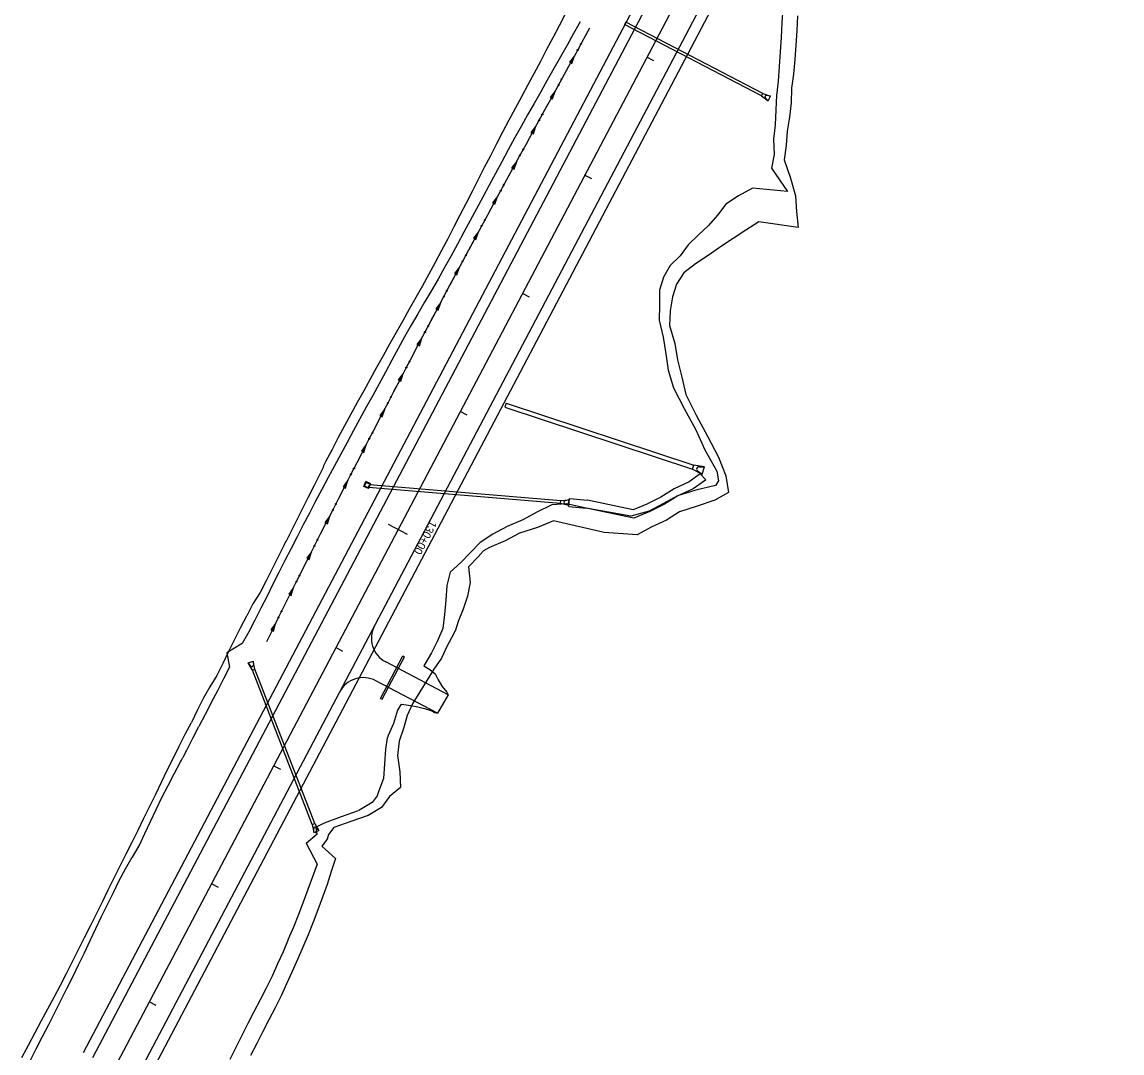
# Model space of a CAD drawing. Extents: x 979959 to 994833, y 1835619 to 1845316.
# Drawn here: x 980649 to 981473, y 1840125 to 1840898 of the extents above; entities that cross this region are included whole.
import ezdxf

# ---------------------------------------------------------------- set-up
doc = ezdxf.new("R2010")
doc.units = 0
for name, color, linetype in [('Future 5 Lane Construction Limits', 7, 'Continuous'), ('R_CONCRETE', 7, 'Continuous'), ('R_Drainage', 7, 'Continuous'), ('R_Horz Alg', 7, 'Continuous'), ('R_Horz Alg Stationing', 7, 'Continuous'), ('R_Proposed Const Limits', 7, 'Continuous'), ('R_Proposed Road', 7, 'Continuous'), ('R_Special Ditch', 7, 'Continuous')]:
    doc.layers.add(name, color=color, linetype=linetype)

msp = doc.modelspace()

# ---------------------------------------------------------------- linework, layer by layer
at = {"layer": 'Future 5 Lane Construction Limits'}
for points in [[(981055.56, 1840903.62), (981050.95, 1840894.75), (981046.29, 1840885.9), (981041.67, 1840877.03), (981037.06, 1840868.16), (981032.36, 1840859.33), (981027.61, 1840850.53), (981022.87, 1840841.72), (981018.11, 1840832.93), (981013.36, 1840824.13), (981008.7, 1840815.28), (981004.1, 1840806.4), (980999.53, 1840797.5), (980994.98, 1840788.6), (980990.43, 1840779.69), (980985.87, 1840770.79), (980981.3, 1840761.9), (980976.71, 1840753.01), (980972.12, 1840744.13), (980967.52, 1840735.25), (980962.84, 1840726.41), (980958.11, 1840717.6), (980953.4, 1840708.78), (980948.57, 1840700.02), (980943.67, 1840691.3), (980938.74, 1840682.59), (980933.82, 1840673.88), (980928.9, 1840665.17), (980924.04, 1840656.43), (980919.16, 1840647.7), (980914.28, 1840638.97), (980909.42, 1840630.22), (980904.6, 1840621.46), (980899.8, 1840612.68), (980894.99, 1840603.92), (980890.17, 1840595.15), (980885.34, 1840586.4), (980881.01, 1840577.37), (980876.25, 1840568.58), (980874.13, 1840564.68), (980874.49, 1840564.48), (980871.99, 1840559.52), (980867.49, 1840550.59), (980862.98, 1840541.66), (980858.48, 1840532.73), (980853.97, 1840523.8), (980849.48, 1840514.86), (980846.12, 1840508.22), (980846.11, 1840508.21), (980844.96, 1840505.94), (980840.44, 1840497.02), (980835.94, 1840488.09), (980831.47, 1840479.14), (980826.94, 1840470.22), (980821.56, 1840461.76), (980817, 1840452.86), (980816.8, 1840452.46), (980812.33, 1840444.01), (980807.66, 1840435.17), (980803.21, 1840426.21), (980798.92, 1840417.17), (980794.59, 1840408.15), (980789.2, 1840399.68), (980784.26, 1840390.98), (980779.89, 1840381.98), (980775.45, 1840373.02)], [(981229.7, 1840902.3), (981229.04, 1840891.35), (981228.4, 1840880.38), (981227.58, 1840869.51), (981226.65, 1840858.7), (981225.19, 1840848.16), (981224.87, 1840837.03), (981223.58, 1840826.4), (981221.83, 1840816.02), (981221.16, 1840805.07), (981219.74, 1840794.52), (981224.45, 1840780.74), (981228.2, 1840767.45), (981228.99, 1840755.73), (981230.27, 1840743.76), (981200.73, 1840748.02), (981191.01, 1840741.84), (981181.48, 1840735.56), (981171.98, 1840729.26), (981162.65, 1840722.87), (981153.26, 1840716.51), (981144.57, 1840709.79), (981139.09, 1840701.37), (981136, 1840691.7), (981134.13, 1840681.38), (981133.68, 1840670.31), (981137.75, 1840656.87), (981139.71, 1840644.53), (981142.86, 1840631.57), (981145.93, 1840618.65), (981153.83, 1840603.18), (981162.31, 1840587.41), (981170.48, 1840571.8), (981176, 1840557.59), (981177.84, 1840545.32), (981167.61, 1840539.41), (981154.48, 1840535.02), (981141.28, 1840530.68), (981131.54, 1840524.5), (981119.96, 1840519.3), (981109.47, 1840513.53), (981084.88, 1840515.18), (981046.7, 1840523.99), (981034.76, 1840518.98), (981021.31, 1840514.76), (981010.58, 1840509.11), (980998.75, 1840504.04), (980994.24, 1840501.4), (980994.23, 1840501.39), (980990.38, 1840497.14), (980983.21, 1840489.62)], [(980983.21, 1840489.62), (980984.39, 1840477.69), (980982.33, 1840467.48), (980979.2, 1840457.83), (980975.42, 1840448.51), (980973.01, 1840441.36), (980973, 1840441.35), (980971.91, 1840439.06), (980967.19, 1840430.24), (980962.98, 1840421.16), (980957.12, 1840412.94), (980951.92, 1840404.38), (980946.71, 1840395.82), (980941.31, 1840387.36), (980941.05, 1840386.99), (980937.21, 1840378.22), (980934.43, 1840368.38), (980931.15, 1840358.81), (980929.87, 1840348.18), (980931.77, 1840335.88), (980932.22, 1840324.34), (980923.96, 1840317.38), (980918.04, 1840309.2), (980907.88, 1840303.25)], [(980648.53, 1840121.92), (980653.39, 1840131.31), (980658.41, 1840140.61), (980663.2, 1840149.58), (980667.89, 1840158.41), (980672.57, 1840167.26), (980677.26, 1840176.08), (980681.96, 1840184.91), (980686.45, 1840193.85), (980690.91, 1840202.8), (980695.37, 1840211.76), (980699.82, 1840220.71), (980704.27, 1840229.67), (980708.74, 1840238.62), (980713.21, 1840247.57), (980717.69, 1840256.51), (980722.15, 1840265.47), (980726.59, 1840274.43), (980731.04, 1840283.39), (980735.49, 1840292.35), (980739.92, 1840301.31), (980744.36, 1840310.28), (980748.76, 1840319.27), (980753.09, 1840328.28), (980757.43, 1840337.3), (980758.97, 1840340.5), (980761.78, 1840346.31), (980763.44, 1840349.54), (980766.36, 1840355.2), (980770.9, 1840364.11), (980775.45, 1840373.02)], [(980907.85, 1840303.26), (980894.83, 1840298.82), (980882.24, 1840294.15), (980878.31, 1840289.02), (980877.27, 1840285.47), (980873.17, 1840280.34), (980883.41, 1840270.93), (980880.32, 1840261.25), (980877.23, 1840251.58), (980873.7, 1840242.14), (980870.18, 1840232.69), (980866.65, 1840223.24), (980862.99, 1840213.87), (980855.02, 1840195.47), (980850.94, 1840186.31), (980846.85, 1840177.16), (980842.66, 1840168.06), (980838.16, 1840159.14), (980833.62, 1840150.22), (980829, 1840141.35), (980824.38, 1840132.48), (980819.86, 1840123.56)]]:
    msp.add_lwpolyline(points, dxfattribs=at)
at = {"layer": 'R_CONCRETE'}
msp.add_line((981058.23, 1840534.72), (981058.73, 1840540.7), dxfattribs=at)
msp.add_lwpolyline([(981160.86, 1840554.64), (981160.61, 1840554.4), (981151.49, 1840547.9), (981139.98, 1840542.66), (981130.1, 1840536.57), (981119.12, 1840531.04), (981107.05, 1840526.1), (981071.35, 1840533.61)], dxfattribs=at)
at = {"layer": 'R_Drainage'}
for p, q in [((981101.01, 1840897.65), (981100.08, 1840895.88)), ((981202.67, 1840842.3), (981100.08, 1840895.88)), ((981203.6, 1840844.07), (981101.01, 1840897.65)), ((981202.67, 1840842.3), (981203.6, 1840844.07)), ((981202.67, 1840842.3), (981207.64, 1840838.58)), ((981203.6, 1840844.07), (981209.49, 1840842.12)), ((981209.49, 1840842.12), (981206.59, 1840842.63)), ((981207.64, 1840838.58), (981209.49, 1840842.12)), ((981207.64, 1840838.58), (981205.57, 1840840.66)), ((981011.32, 1840612.03), (981010.38, 1840609.18)), ((981011.32, 1840612.03), (981151.87, 1840565.66)), ((981010.38, 1840609.18), (981150.93, 1840562.82)), ((981150.93, 1840562.82), (981151.87, 1840565.66)), ((981150.93, 1840562.82), (981158.2, 1840558.84)), ((981160.08, 1840564.54), (981151.87, 1840565.66)), ((981154.72, 1840561.49), (981158.2, 1840558.84)), ((981155.71, 1840564.48), (981160.08, 1840564.54)), ((981158.2, 1840558.84), (981160.08, 1840564.54)), ((980904.59, 1840549.8), (980906.24, 1840553.44)), ((980905.25, 1840550.05), (980906.49, 1840552.78)), ((980909.88, 1840551.8), (980906.24, 1840553.44)), ((980909.22, 1840551.55), (980906.49, 1840552.78)), ((981156.84, 1840559.09), (981160.86, 1840554.64)), ((980908.24, 1840548.15), (980904.59, 1840549.8)), ((980907.99, 1840548.81), (980905.25, 1840550.05)), ((980907.99, 1840548.81), (980909.22, 1840551.55)), ((980908.17, 1840549.21), (981052.02, 1840537.18)), ((980908.24, 1840548.15), (980909.88, 1840551.8)), ((980909.04, 1840551.15), (981052.19, 1840539.17)), ((981052.02, 1840537.18), (981052.19, 1840539.17)), ((981052.02, 1840537.18), (981058.04, 1840535.67)), ((981052.19, 1840539.17), (981058.37, 1840539.66)), ((981058.04, 1840535.67), (981055.32, 1840536.79)), ((981058.37, 1840539.66), (981055.5, 1840539)), ((981058.04, 1840535.67), (981058.37, 1840539.66)), ((981058.73, 1840540.7), (981072.22, 1840539.56)), ((981058.23, 1840534.72), (981071.35, 1840533.61)), ((980917.1, 1840391.02), (980933.88, 1840422.87)), ((980918.43, 1840390.32), (980935.21, 1840422.17)), ((980933.88, 1840422.87), (980935.21, 1840422.17)), ((980818.02, 1840417.52), (980821.75, 1840418.97)), ((980821.17, 1840412.18), (980818.02, 1840417.52)), ((980818.02, 1840417.52), (980819.86, 1840415.23)), ((980821.17, 1840412.18), (980823.03, 1840412.9)), ((980823.03, 1840412.9), (980821.75, 1840418.97)), ((980821.75, 1840418.97), (980821.93, 1840416.04)), ((980867.91, 1840297.31), (980823.03, 1840412.9)), ((980866.04, 1840296.58), (980821.17, 1840412.18)), ((980917.1, 1840391.02), (980918.43, 1840390.32)), ((980866.04, 1840296.58), (980867.91, 1840297.31)), ((980867.91, 1840297.31), (980871.06, 1840291.97)), ((980866.04, 1840296.58), (980867.34, 1840290.52)), ((980867.34, 1840290.52), (980867.15, 1840293.45)), ((980867.34, 1840290.52), (980871.06, 1840291.97)), ((980871.06, 1840291.97), (980869.22, 1840294.25))]:
    msp.add_line(p, q, dxfattribs=at)
msp.add_lwpolyline([(981156.84, 1840559.09), (981148.47, 1840553.12), (981137.15, 1840547.97), (981127.17, 1840541.81), (981116.63, 1840536.51), (981106.48, 1840532.35), (981072.22, 1840539.56)], dxfattribs=at)
for centre, radius, start, end in [((981206.39, 1840841.49), 1.17, 79.95056, 224.89072), ((981155.73, 1840562.81), 1.67, 90.78401, 232.69877), ((981055.76, 1840537.87), 1.17, 102.74744, 247.68759), ((980820.77, 1840415.96), 1.17, 218.74744, 3.68759), ((980868.31, 1840293.53), 1.17, 38.85574, 183.79589)]:
    msp.add_arc(centre, radius, start, end, dxfattribs=at)
at = {"layer": 'R_Horz Alg'}
msp.add_line((981456.9, 1841516.96), (980717.33, 1840113.21), dxfattribs=at)
at = {"layer": 'R_Horz Alg Stationing'}
for points in [[(981122.08, 1840868.58), (981116.77, 1840871.37)], [(981075.47, 1840780.1), (981070.16, 1840782.9)], [(981028.85, 1840691.63), (981023.55, 1840694.43)], [(980982.24, 1840603.16), (980976.93, 1840605.96)], [(980937.4, 1840513.76), (980923.24, 1840521.21)], [(980889.02, 1840426.22), (980883.71, 1840429.01)], [(980842.41, 1840337.74), (980837.1, 1840340.54)], [(980795.8, 1840249.27), (980790.49, 1840252.07)], [(980749.18, 1840160.8), (980743.88, 1840163.6)]]:
    msp.add_lwpolyline(points, dxfattribs=at)
at = {"layer": 'R_Proposed Const Limits'}
for p, q in [((981066.72, 1840897.74), (981061.84, 1840889.01)), ((980818.53, 1840440.75), (980813.54, 1840432.07))]:
    msp.add_line(p, q, dxfattribs=at)
for points in [[(981211.65, 1840945.72), (981220.18, 1840929.92), (981219.46, 1840919), (981218.75, 1840908.07), (981218.03, 1840897.14), (981217.33, 1840886.21), (981216.65, 1840875.27), (981215.9, 1840864.36), (981215.11, 1840853.47), (981213.99, 1840842.76)], [(981069.5, 1840884.98), (981074.05, 1840893.29)], [(981061.84, 1840889.01), (981056.94, 1840880.29), (981052.05, 1840871.56), (981047.14, 1840862.85), (981042.19, 1840854.15), (981037.24, 1840845.45), (981032.32, 1840836.75), (981027.39, 1840828.04), (981022.46, 1840819.33), (981017.59, 1840810.59), (981012.81, 1840801.81), (981008.03, 1840793.03), (981003.28, 1840784.23), (980998.6, 1840775.39), (980993.86, 1840766.58), (980989.14, 1840757.77), (980984.38, 1840748.97), (980979.65, 1840740.16), (980974.9, 1840731.36), (980970.06, 1840722.61), (980965.14, 1840713.9), (980960.27, 1840705.16), (980955.32, 1840696.46), (980950.2, 1840687.86), (980945.21, 1840679.19), (980940.24, 1840670.5), (980935.28, 1840661.81), (980930.47, 1840653.04), (980925.7, 1840644.25), (980920.88, 1840635.49), (980916.12, 1840626.69), (980911.35, 1840617.91), (980906.55, 1840609.13), (980901.77, 1840600.35), (980897.01, 1840591.55), (980892.24, 1840582.76), (980887.48, 1840573.96), (980882.73, 1840565.16), (980878, 1840556.35), (980873.27, 1840547.54), (980868.55, 1840538.73), (980863.94, 1840529.85), (980859.31, 1840520.99), (980854.73, 1840512.1), (980850.14, 1840503.21), (980845.58, 1840494.31), (980841.03, 1840485.41), (980836.58, 1840476.45), (980832.14, 1840467.48), (980827.59, 1840458.58), (980823.12, 1840449.63), (980818.53, 1840440.75)], [(980831.91, 1840433.7), (980836.38, 1840442.65), (980840.84, 1840451.6), (980845.3, 1840460.55), (980849.78, 1840469.5), (980854.26, 1840478.44), (980858.76, 1840487.37), (980863.26, 1840496.3), (980867.77, 1840505.23), (980872.29, 1840514.15), (980876.81, 1840523.07), (980881.35, 1840531.98), (980885.89, 1840540.89), (980890.45, 1840549.8), (980895.01, 1840558.7), (980895.05, 1840558.77), (980899.58, 1840567.59), (980904.16, 1840576.48), (980908.74, 1840585.37), (980913.34, 1840594.25), (980917.94, 1840603.13), (980920.62, 1840608.28), (980922.56, 1840612), (980927.18, 1840620.87), (980931.81, 1840629.73), (980936.45, 1840638.59), (980941.1, 1840647.44), (980945.75, 1840656.29), (980950.42, 1840665.14), (980952.4, 1840668.88), (980955.09, 1840673.98), (980959.77, 1840682.82), (980964.46, 1840691.65), (980969.16, 1840700.47), (980973.87, 1840709.3), (980978.59, 1840718.11), (980983.31, 1840726.93), (980988.05, 1840735.74), (980992.79, 1840744.54), (980997.54, 1840753.34), (981002.3, 1840762.14), (981007.07, 1840770.93), (981011.85, 1840779.71), (981016.63, 1840788.49), (981021.43, 1840797.27), (981026.23, 1840806.04), (981031.04, 1840814.81), (981035.85, 1840823.58), (981040.65, 1840832.35), (981045.46, 1840841.12), (981050.27, 1840849.89), (981055.08, 1840858.67), (981059.88, 1840867.44), (981064.69, 1840876.21), (981069.5, 1840884.98)], [(981213.99, 1840842.76), (981213.66, 1840837.28), (981213.38, 1840831.78), (981212.83, 1840820.77), (981211.78, 1840810.01), (981212.22, 1840798.48), (981210.2, 1840788.24), (981222.04, 1840770.7), (981195.83, 1840773.21), (981185.44, 1840767.38), (981175.88, 1840761.11), (981169.8, 1840753.01), (981163.07, 1840745.25), (981155.33, 1840738.03), (981147.67, 1840730.76), (981141.75, 1840722.58), (981134.17, 1840715.27), (981129.2, 1840706.59), (981126.21, 1840696.86), (981126.27, 1840685.52), (981125.96, 1840674.38), (981128.88, 1840661.54), (981131, 1840649.12), (981132.76, 1840636.89), (981136.69, 1840623.52), (981144.62, 1840608.04), (981153.48, 1840592.07), (981160.22, 1840577.21), (981169.1, 1840561.23), (981170.55, 1840553.95), (981168.25, 1840550.37), (981153.37, 1840546.91), (981139.77, 1840542.77), (981129.17, 1840537.05), (981118.62, 1840531.31), (981104.65, 1840527.37), (981071.39, 1840533.58), (981056.67, 1840536.61), (981045.58, 1840535.88), (981034.43, 1840530.45), (981023.78, 1840524.76), (981011.97, 1840519.68), (981001.47, 1840513.91), (980991.93, 1840507.73), (980991.86, 1840507.67), (980984.52, 1840500.24), (980977.26, 1840492.76), (980969.4, 1840485.59)], [(980969.4, 1840485.59), (980966.88, 1840475.62), (980966.24, 1840464.65), (980965.22, 1840453.89), (980963.77, 1840443.35), (980959.84, 1840434.12), (980955.47, 1840425.11), (980950.31, 1840416.53), (980949.62, 1840415.49)], [(980813.54, 1840432.07), (980802, 1840425.09), (980804.14, 1840414.42), (980799.52, 1840405.55), (980794.93, 1840396.67), (980790.33, 1840387.79), (980788.51, 1840384.28), (980785.73, 1840378.91), (980781.13, 1840370.03)], [(980949.62, 1840415.49), (980954.25, 1840412.73), (980958.09, 1840409.28), (980960.35, 1840405), (980963.43, 1840400), (980966.9, 1840395.76), (980967.79, 1840393.76)], [(980932.74, 1840386.65), (980929.95, 1840382.05), (980927.01, 1840372.29), (980923.03, 1840363.09), (980922.37, 1840361.67), (980922.21, 1840361.33), (980922.2, 1840361.32), (980920.81, 1840352.95), (980920.19, 1840341.98), (980919.4, 1840331.09), (980915.92, 1840321.62), (980914.57, 1840317.87), (980910.84, 1840312.99), (980900.95, 1840306.9)], [(980932.74, 1840386.65), (980934.75, 1840386.44), (980939.99, 1840385.65), (980945.09, 1840384.61), (980950.15, 1840383.5), (980954.92, 1840381.82), (980957.71, 1840380.36), (980959.83, 1840379.87)], [(980654.5, 1840118.93), (980659.21, 1840128.33), (980663.99, 1840137.69), (980668.59, 1840146.75), (980673.1, 1840155.67), (980677.62, 1840164.59), (980682.13, 1840173.52), (980686.59, 1840182.47), (980690.97, 1840191.47), (980695.35, 1840200.46), (980699.56, 1840209.55), (980703.88, 1840218.58), (980708.2, 1840227.6), (980712.58, 1840236.6), (980716.99, 1840245.58), (980721.34, 1840254.59), (980726.09, 1840263.39), (980731.2, 1840272), (980731.23, 1840272.04), (980736.38, 1840280.58), (980740.56, 1840289.67), (980744.75, 1840298.77), (980748.98, 1840307.84), (980753.39, 1840316.82), (980758.04, 1840325.68), (980762.68, 1840334.54), (980767.32, 1840343.39), (980767.95, 1840344.59), (980769.01, 1840346.61), (980769.21, 1840346.98), (980771.95, 1840352.26), (980776.55, 1840361.14), (980781.13, 1840370.03)], [(980861.48, 1840282.48), (980869.63, 1840289.49), (980869.35, 1840291.16), (980868.88, 1840293.99), (980868.79, 1840294.51), (980875.32, 1840297.8), (980887.93, 1840302.46), (980900.76, 1840307)], [(980869.15, 1840293.85), (980868.83, 1840289.92)], [(980861.48, 1840282.48), (980869.79, 1840266.8), (980866.29, 1840257.34), (980862.78, 1840247.89), (980859.28, 1840238.43), (980855.78, 1840228.97), (980852.02, 1840219.65), (980848.08, 1840210.48), (980848.06, 1840210.43), (980844.19, 1840201.17), (980839.94, 1840192.1), (980835.96, 1840182.9), (980831.6, 1840173.89), (980826.88, 1840165.08), (980822.34, 1840156.17), (980817.71, 1840147.3), (980813.2, 1840138.37), (980808.76, 1840129.41), (980804.17, 1840120.53)]]:
    msp.add_lwpolyline(points, dxfattribs=at)
at = {"layer": 'R_Proposed Road'}
for p, q in [((981440.97, 1841525.35), (980701.4, 1840121.6)), ((981472.82, 1841508.57), (980733.25, 1840104.82)), ((981337, 1841345.16), (980694.33, 1840125.33)), ((981371.29, 1841298.7), (980740.33, 1840101.09)), ((980967.79, 1840393.76), (980959.83, 1840379.87))]:
    msp.add_line(p, q, dxfattribs=at)
for points in [[(980967.79, 1840393.76), (980921.06, 1840418.38)], [(980959.83, 1840379.87), (980913.6, 1840404.22)]]:
    msp.add_lwpolyline(points, dxfattribs=at)
for centre, start, end in [((980930.38, 1840436.07), 152.21752, 242.21752), ((980904.28, 1840386.53), 62.21752, 152.21752)]:
    msp.add_arc(centre, 20, start, end, dxfattribs=at)
at = {"layer": 'R_Special Ditch'}
for p, q in [((981062.56, 1840872.32), (981058.75, 1840867.56)), ((981058.75, 1840867.56), (981060.6, 1840866.55)), ((981060.6, 1840866.55), (981062.56, 1840872.32)), ((981048.12, 1840845.98), (981044.31, 1840841.22)), ((981044.31, 1840841.22), (981046.16, 1840840.21)), ((981046.16, 1840840.21), (981048.12, 1840845.98)), ((981033.68, 1840819.64), (981029.87, 1840814.88)), ((981031.73, 1840813.87), (981033.68, 1840819.64)), ((981029.87, 1840814.88), (981031.73, 1840813.87)), ((981019.25, 1840793.29), (981015.45, 1840788.53)), ((981017.31, 1840787.52), (981019.25, 1840793.29)), ((981015.45, 1840788.53), (981017.31, 1840787.52)), ((981004.89, 1840766.91), (981001.1, 1840762.14)), ((981002.96, 1840761.13), (981004.89, 1840766.91)), ((981001.1, 1840762.14), (981002.96, 1840761.13)), ((980990.61, 1840740.48), (980986.83, 1840735.7)), ((980986.83, 1840735.7), (980988.69, 1840734.7)), ((980988.69, 1840734.7), (980990.61, 1840740.48)), ((980976.4, 1840714.02), (980972.64, 1840709.23)), ((980972.64, 1840709.23), (980974.5, 1840708.23)), ((980974.5, 1840708.23), (980976.4, 1840714.02)), ((980962.27, 1840687.51), (980958.52, 1840682.71)), ((980960.39, 1840681.72), (980962.27, 1840687.51)), ((980958.52, 1840682.71), (980960.39, 1840681.72)), ((980948.22, 1840660.96), (980944.48, 1840656.15)), ((980946.35, 1840655.16), (980948.22, 1840660.96)), ((980944.48, 1840656.15), (980946.35, 1840655.16)), ((980934.24, 1840634.37), (980930.52, 1840629.55)), ((980930.52, 1840629.55), (980932.39, 1840628.57)), ((980932.39, 1840628.57), (980934.24, 1840634.37)), ((980920.34, 1840607.74), (980916.64, 1840602.91)), ((980916.64, 1840602.91), (980918.52, 1840601.93)), ((980918.52, 1840601.93), (980920.34, 1840607.74)), ((980906.53, 1840581.07), (980902.83, 1840576.23)), ((980904.71, 1840575.26), (980906.53, 1840581.07)), ((980902.83, 1840576.23), (980904.71, 1840575.26)), ((980892.79, 1840554.36), (980889.11, 1840549.51)), ((980890.99, 1840548.54), (980892.79, 1840554.36)), ((980889.11, 1840549.51), (980890.99, 1840548.54)), ((980879.12, 1840527.61), (980875.46, 1840522.74)), ((980875.46, 1840522.74), (980877.34, 1840521.78)), ((980877.34, 1840521.78), (980879.12, 1840527.61)), ((980865.54, 1840500.82), (980861.89, 1840495.94)), ((980861.89, 1840495.94), (980863.78, 1840494.99)), ((980863.78, 1840494.99), (980865.54, 1840500.82)), ((980852.03, 1840473.99), (980848.4, 1840469.1)), ((980850.29, 1840468.15), (980852.03, 1840473.99)), ((980848.4, 1840469.1), (980850.29, 1840468.15)), ((980838.6, 1840447.12), (980834.98, 1840442.22)), ((980836.87, 1840441.28), (980838.6, 1840447.12)), ((980834.98, 1840442.22), (980836.87, 1840441.28))]:
    msp.add_line(p, q, dxfattribs=at)
for points in [[(981069.79, 1840885.5), (981074.05, 1840893.29)], [(981069.77, 1840885.47), (981069.79, 1840885.5)], [(981055.35, 1840859.16), (981059.88, 1840867.44), (981062.56, 1840872.32)], [(981055.33, 1840859.13), (981055.35, 1840859.16)], [(981040.91, 1840832.82), (981045.46, 1840841.12), (981048.12, 1840845.98)], [(981040.89, 1840832.79), (981040.91, 1840832.82)], [(981026.47, 1840806.48), (981031.04, 1840814.81), (981033.68, 1840819.64)], [(981026.45, 1840806.45), (981026.47, 1840806.48)], [(981012.07, 1840780.12), (981016.63, 1840788.49), (981019.25, 1840793.29)], [(981012.05, 1840780.09), (981012.07, 1840780.12)], [(980997.75, 1840753.72), (981002.3, 1840762.14), (981004.89, 1840766.91)], [(980997.73, 1840753.69), (980997.75, 1840753.72)], [(980983.5, 1840727.27), (980988.05, 1840735.74), (980990.61, 1840740.48)], [(980983.48, 1840727.24), (980983.5, 1840727.27)], [(980969.33, 1840700.79), (980973.87, 1840709.3), (980976.4, 1840714.02)], [(980969.31, 1840700.75), (980969.33, 1840700.79)], [(980955.24, 1840674.26), (980959.77, 1840682.82), (980962.27, 1840687.51)], [(980955.22, 1840674.23), (980955.24, 1840674.26)], [(980941.23, 1840647.69), (980945.75, 1840656.29), (980948.22, 1840660.96)], [(980941.21, 1840647.66), (980941.23, 1840647.69)], [(980927.29, 1840621.08), (980931.81, 1840629.73), (980934.24, 1840634.37)], [(980927.27, 1840621.05), (980927.29, 1840621.08)], [(980913.43, 1840594.43), (980917.94, 1840603.13), (980920.34, 1840607.74)], [(980913.42, 1840594.4), (980913.43, 1840594.43)], [(980899.65, 1840567.74), (980904.16, 1840576.48), (980906.53, 1840581.07)], [(980899.64, 1840567.71), (980899.65, 1840567.74)], [(980885.95, 1840541.01), (980890.45, 1840549.8), (980892.79, 1840554.36)], [(980885.93, 1840540.98), (980885.95, 1840541.01)], [(980872.33, 1840514.24), (980876.81, 1840523.07), (980879.12, 1840527.61)], [(980872.31, 1840514.2), (980872.33, 1840514.24)], [(980858.78, 1840487.43), (980863.26, 1840496.3), (980865.54, 1840500.82)], [(980858.77, 1840487.39), (980858.78, 1840487.43)], [(980845.32, 1840460.58), (980849.78, 1840469.5), (980852.03, 1840473.99)], [(980845.3, 1840460.54), (980845.3, 1840460.55), (980845.32, 1840460.58)], [(980831.91, 1840433.7), (980836.38, 1840442.65), (980838.6, 1840447.12)]]:
    msp.add_lwpolyline(points, dxfattribs=at)
for centre in [(981064.93, 1840876.72), (981067.34, 1840881.12), (981050.5, 1840850.38), (981052.9, 1840854.78), (981038.46, 1840828.44), (981036.06, 1840824.04), (981024.03, 1840802.09), (981021.62, 1840797.7), (981009.64, 1840775.73), (981007.25, 1840771.33), (980992.95, 1840744.91), (980995.33, 1840749.32), (980978.73, 1840718.45), (980981.1, 1840722.87), (980966.94, 1840696.37), (980964.58, 1840691.95), (980952.86, 1840669.84), (980950.52, 1840665.41), (980938.86, 1840643.26), (980936.53, 1840638.83), (980922.62, 1840612.2), (980924.94, 1840616.65), (980908.79, 1840585.54), (980911.09, 1840589.99), (980897.33, 1840563.29), (980895.04, 1840558.83), (980883.64, 1840536.55), (980881.36, 1840532.09), (980867.76, 1840505.3), (980870.03, 1840509.77), (980854.25, 1840478.48), (980856.5, 1840482.96), (980843.04, 1840456.1), (980840.81, 1840451.62)]:
    msp.add_circle(centre, 0.375, dxfattribs=at)

# ---------------------------------------------------------------- texts
at = {"layer": 'R_Horz Alg Stationing'}
msp.add_text('130+00', height=6, rotation=242.21752, dxfattribs=at).set_placement((980954.47, 1840524.71))

doc.saveas('drawing.dxf')
